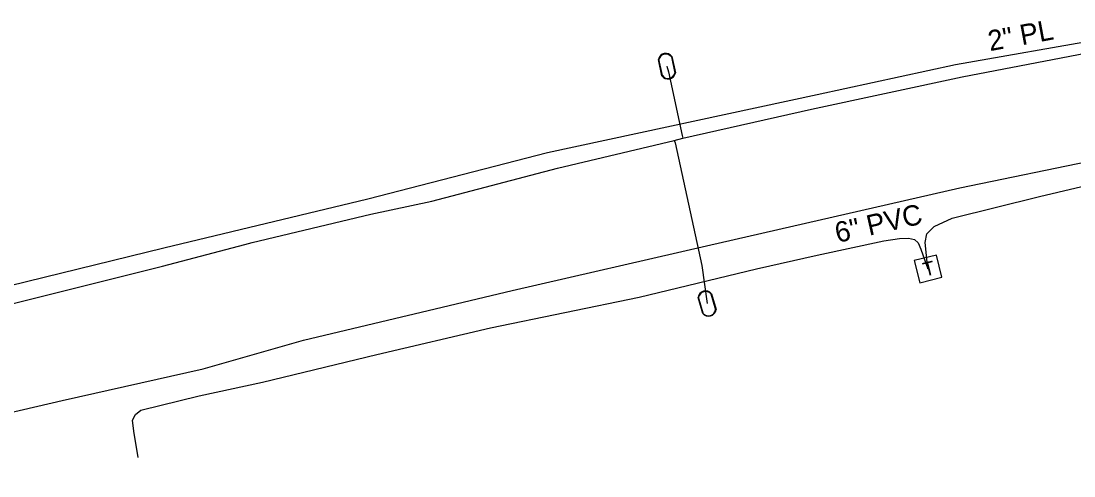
# Model space of a CAD drawing. Extents: x 1614427 to 1617186, y 896524 to 905462.
# Drawn here: x 1615609.8 to 1615867.8, y 900049.3 to 900160.7 of the extents above; entities that cross this region are included whole.
import ezdxf

# ---------------------------------------------------------------- set-up
doc = ezdxf.new("R2010")
doc.units = 0
for name, color, linetype in [('Exist Utilities Gas UG Line SUE LOS B', 7, 'Continuous'), ('Exist Utilities Gas UG Line SUE LOS B Text', 7, 'Continuous'), ('Exist Utilities Sanitary Sewer Forced Main SUE LOS C', 7, 'Continuous'), ('Exist Utilities Sanitary Sewer Forced Main SUE LOS C Text', 7, 'Continuous'), ('Exist Utilities Telephone Pedestal CELL', 7, 'Continuous'), ('Exist Utilities Telephone UG Cable SUE LOS C', 7, 'Continuous'), ('Exist Utilities Water Meter CELL', 7, 'Continuous'), ('Exist Utilities Water UG Line SUE LOS B', 7, 'Continuous')]:
    doc.layers.add(name, color=color, linetype=linetype)

msp = doc.modelspace()

# ---------------------------------------------------------------- linework, layer by layer
at = {"layer": 'Exist Utilities Gas UG Line SUE LOS B'}
msp.add_lwpolyline([(1615602.7, 900094.85), (1615644.71, 900105.16), (1615694.71, 900117.16), (1615738.8, 900128.49), (1615804.89, 900142.78), (1615838.75, 900150.07), (1615875.16, 900156.5), (1615921.07, 900160.55), (1615953.5, 900159.47), (1615984.36, 900155.27), (1616020.46, 900149.59), (1616075.34, 900139.23), (1616125.54, 900129.96), (1616163.6, 900121.29), (1616208.7, 900112.75), (1616241.8, 900106.59), (1616257.56, 900109.56), (1616267.97, 900109.75), (1616269.03, 900109.71), (1616270.66, 900110.37)], dxfattribs=at)
at = {"layer": 'Exist Utilities Sanitary Sewer Forced Main SUE LOS C'}
msp.add_lwpolyline([(1615599.7, 900063.1), (1615619.8, 900067.73), (1615654.39, 900075.53), (1615679.01, 900082.53), (1615730.11, 900094.67), (1615777.77, 900105.66), (1615839.81, 900119.84), (1615873.91, 900126.87), (1615879.61, 900127), (1615895.95, 900128.76), (1615921.39, 900129.89), (1615932.33, 900130.37), (1615962.5, 900127.93), (1615996.95, 900123.07), (1616029.07, 900117.94), (1616050.03, 900113.65), (1616071.5, 900109.18), (1616143.09, 900093.88), (1616176.95, 900086.31), (1616208.03, 900078.35), (1616239.83, 900068.88), (1616305.38, 900049.26)], dxfattribs=at)
at = {"layer": 'Exist Utilities Telephone Pedestal CELL'}
msp.add_line((1615831.98, 900100.01), (1615831.98, 900100.01), dxfattribs=at)
msp.add_lwpolyline([(1615830.01, 900096.62), (1615835.44, 900097.95), (1615834.11, 900103.38), (1615828.68, 900102.05), (1615830.01, 900096.62)], dxfattribs=at)
at = {"layer": 'Exist Utilities Telephone UG Cable SUE LOS C'}
for points in [[(1615831.98, 900100.01), (1615831.32, 900106.5), (1615831.78, 900108.56), (1615833.55, 900110.39), (1615838, 900112.46), (1615859.37, 900117.72), (1615874.25, 900121.22), (1615886.86, 900124.2), (1615923.03, 900126.44), (1615950.4, 900125.56), (1615990.86, 900120.34), (1616033.24, 900112.71), (1616040.14, 900111.41), (1616043.65, 900109.9), (1616045.95, 900108.2), (1616046.15, 900106.5), (1616046.08, 900103.84), (1616045.66, 900098.32)], [(1615638.46, 900053.75), (1615637.43, 900060.19), (1615637.08, 900062.93), (1615637.83, 900064.31), (1615639.14, 900065.34), (1615653.44, 900068.87), (1615668.92, 900072.25), (1615696.97, 900079.06), (1615724.82, 900085.54), (1615761.25, 900093.08), (1615789.97, 900100.05), (1615804.86, 900103.38), (1615821.23, 900106.85), (1615825.03, 900107.45), (1615827.27, 900107.51), (1615828.75, 900107.22), (1615829.61, 900106.42), (1615830.3, 900104.82), (1615831.98, 900100.01)]]:
    msp.add_lwpolyline(points, dxfattribs=at)
at = {"layer": 'Exist Utilities Water Meter CELL'}
for p, q in [((1615768.04, 900149.67), (1615768.04, 900149.67)), ((1615777.89, 900091.5), (1615777.89, 900091.5))]:
    msp.add_line(p, q, dxfattribs=at)
for points in [[(1615766.79, 900147.33), (1615765.95, 900151.34)], [(1615766.93, 900147.36), (1615766.09, 900151.37)], [(1615769.15, 900151.99), (1615769.99, 900148)], [(1615769.29, 900152.02), (1615770.12, 900148.03)], [(1615776.82, 900089.07), (1615775.69, 900093.01)], [(1615776.95, 900089.11), (1615775.82, 900093.05)], [(1615778.84, 900093.89), (1615779.95, 900089.97)], [(1615778.97, 900093.92), (1615780.09, 900090.01)]]:
    msp.add_lwpolyline(points, dxfattribs=at)
for centre, radius, start, end in [((1615767.77, 900150.95), 1.86, 34.9957, 167.7971), ((1615767.77, 900150.94), 1.73, 37.1186, 165.6), ((1615768.31, 900148.41), 1.86, 215.466, 348.126), ((1615768.31, 900148.4), 1.73, 216.9448, 346.6905), ((1615777.53, 900092.75), 1.86, 39.1055, 171.9069), ((1615777.53, 900092.74), 1.73, 41.2284, 169.7098), ((1615778.25, 900090.26), 1.86, 219.5758, 352.2358), ((1615778.25, 900090.24), 1.73, 221.0546, 350.8003)]:
    msp.add_arc(centre, radius, start, end, dxfattribs=at)
at = {"layer": 'Exist Utilities Water UG Line SUE LOS B'}
for points in [[(1615603.86, 900090.52), (1615644.4, 900100.68), (1615664.61, 900105.95), (1615666.39, 900106.44), (1615695.49, 900113.41), (1615710.42, 900116.62), (1615741.25, 900124.72), (1615769.85, 900131.48), (1615771.96, 900132), (1615803.48, 900139.11), (1615840.37, 900147.07), (1615872.74, 900153.26), (1615921.05, 900157.88), (1615953.34, 900156.02), (1615980.61, 900152.41), (1615993.99, 900150.57), (1616019.44, 900146.45), (1616079.92, 900133.8), (1616088.66, 900131.47), (1616092.71, 900130.59), (1616148.84, 900119.1)], [(1615768.04, 900149.67), (1615768.41, 900148.33), (1615771.79, 900132.73), (1615771.96, 900132)], [(1615769.85, 900131.48), (1615770.03, 900130.9), (1615776.64, 900100.82), (1615777.89, 900091.5)]]:
    msp.add_lwpolyline(points, dxfattribs=at)

# ---------------------------------------------------------------- texts
at = {"layer": 'Exist Utilities Gas UG Line SUE LOS B Text'}
msp.add_text('2" PL', height=5, rotation=10.4943, dxfattribs=at).set_placement((1615847.23, 900153.35))
at = {"layer": 'Exist Utilities Sanitary Sewer Forced Main SUE LOS C Text'}
msp.add_text('6" PVC', height=5, rotation=12.8008, dxfattribs=at).set_placement((1615809.85, 900106.35))
at = {"layer": 'Exist Utilities Telephone Pedestal CELL'}
msp.add_text('T', height=3.42, rotation=13.76, dxfattribs=at).set_placement((1615831.29, 900098.08))

doc.saveas('drawing.dxf')
